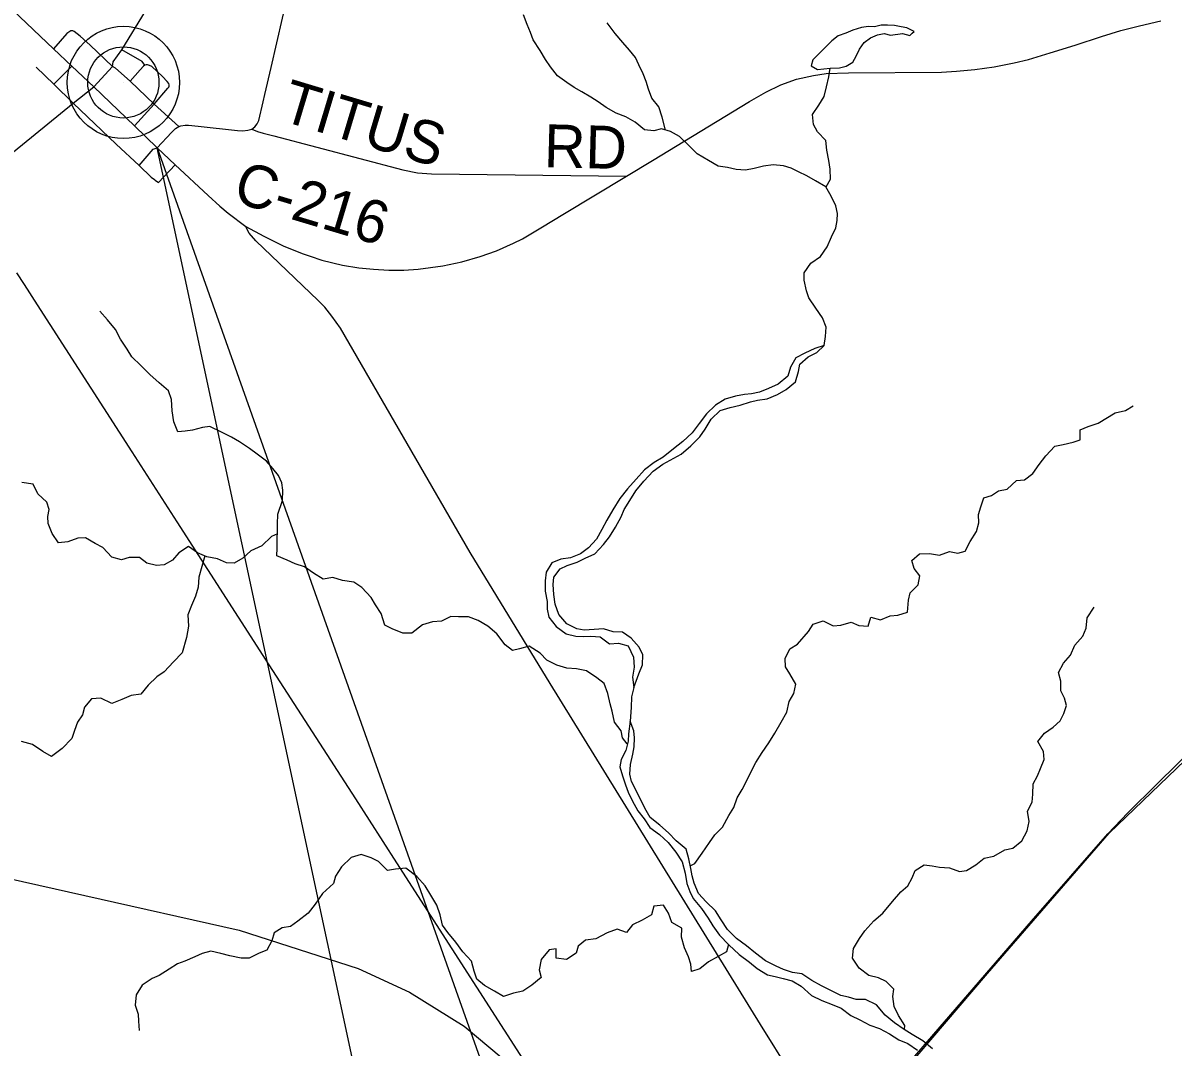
# Model space of a CAD drawing. Extents: x 0 to 34, y 0 to 22.
# Drawn here: x 4.77 to 5.532, y 15.329 to 16.008 of the extents above; entities that cross this region are included whole.
import ezdxf

# ---------------------------------------------------------------- set-up
doc = ezdxf.new("R2010")
doc.units = 0
for name, color, linetype in [('GM_X_County_Road', 7, 'Continuous'), ('GM_X_County_Road_Text', 7, 'Continuous'), ('GM_X_Minor_Lake', 7, 'Continuous'), ('GM_X_Minor_River', 7, 'Continuous'), ('GM_X_Rail_Line', 7, 'Continuous'), ('GM_X_State_Route', 7, 'Continuous'), ('GM_X_Township_Road', 7, 'Continuous'), ('GM_X_Unincorporated', 7, 'Continuous'), ('GM_X_Unincorporated_Location', 7, 'Continuous'), ('SH_Text', 7, 'Continuous')]:
    doc.layers.add(name, color=color, linetype=linetype)

msp = doc.modelspace()

# ---------------------------------------------------------------- linework, layer by layer
at = {"layer": 'GM_X_County_Road'}
for points in [[(4.92188, 15.93736), (4.92553, 15.93572), (4.9293, 15.93457), (4.9363, 15.93294), (5.02191, 15.91045), (5.03158, 15.90846), (5.04097, 15.90761), (5.17016, 15.90625)], [(5.57836, 15.08677), (5.48556, 15.13609), (5.4293, 15.16578), (5.41883, 15.1717), (5.40807, 15.17885), (5.38156, 15.19893), (5.37557, 15.20405), (5.36741, 15.2125), (5.35766, 15.22305), (5.33768, 15.24534), (5.31683, 15.26876), (5.30209, 15.28504), (5.27906, 15.31173), (5.25891, 15.34383), (5.11957, 15.56983), (5.06651, 15.65664), (4.98053, 15.80534), (4.97493, 15.81333), (4.97028, 15.81941), (4.96586, 15.82383), (4.92435, 15.86339), (4.92003, 15.86847), (4.91864, 15.87087), (4.91787, 15.87287)]]:
    msp.add_lwpolyline(points, dxfattribs=at)
at = {"layer": 'GM_X_Minor_Lake'}
for points in [[(5.35947, 16.00091), (5.36068, 16.00195), (5.35595, 16.00443), (5.35216, 16.0052), (5.34781, 16.00598), (5.34308, 16.00618), (5.33891, 16.0062), (5.33455, 16.00526), (5.33057, 16.00528), (5.32583, 16.00473), (5.32014, 16.00285), (5.3154, 16.00097), (5.31047, 15.99909), (5.30629, 15.99588), (5.29355, 15.98321), (5.29259, 15.97923), (5.29674, 15.97694), (5.30508, 15.97767)], [(5.30508, 15.97767), (5.31133, 15.97803), (5.3157, 15.97915), (5.32006, 15.98179), (5.32235, 15.98577), (5.32464, 15.99031), (5.32769, 15.99467), (5.33187, 15.99788), (5.33642, 15.99976), (5.34097, 16.00069), (5.34513, 15.99954), (5.35309, 16.00065), (5.35783, 15.99949), (5.35947, 16.00091)]]:
    msp.add_lwpolyline(points, dxfattribs=at)
at = {"layer": 'GM_X_Minor_River'}
for points in [[(5.30114, 15.79393), (5.30193, 15.79981), (5.30253, 15.80606), (5.29992, 15.81234), (5.29559, 15.81862), (5.2909, 15.82547), (5.28941, 15.83022), (5.28793, 15.83724), (5.28777, 15.84218), (5.29235, 15.84841), (5.29862, 15.85293), (5.30302, 15.85935), (5.30589, 15.86598), (5.30877, 15.87184), (5.30974, 15.87677), (5.30996, 15.88151), (5.30885, 15.88645), (5.30585, 15.89291), (5.30229, 15.89919), (5.2953, 15.90302), (5.28964, 15.90646), (5.28416, 15.90914), (5.27925, 15.91145), (5.27414, 15.91299), (5.26733, 15.91378), (5.26088, 15.91287), (5.25481, 15.9112), (5.24893, 15.91009), (5.24288, 15.9105), (5.23701, 15.91186), (5.23077, 15.91284), (5.22454, 15.91648), (5.21698, 15.92107), (5.21152, 15.92641), (5.2053, 15.93251), (5.19926, 15.93576), (5.1934, 15.9375), (5.18828, 15.9362), (5.18203, 15.9368), (5.17581, 15.94196), (5.16958, 15.94541), (5.16334, 15.9479), (5.15654, 15.95173), (5.15145, 15.95536), (5.14654, 15.95861), (5.1405, 15.96206), (5.1354, 15.96493), (5.1305, 15.96818), (5.12446, 15.97258), (5.11976, 15.97867), (5.11637, 15.98343), (5.11281, 15.98952), (5.1083, 15.99656), (5.10643, 16.0015), (5.10438, 16.00663), (5.10195, 16.01309)], [(5.19594, 15.93675), (5.19376, 15.94525), (5.19152, 15.95208), (5.1868, 15.95798), (5.18474, 15.96387), (5.18324, 15.96899), (5.18118, 15.97393), (5.17836, 15.98001), (5.1761, 15.98476), (5.17215, 15.98971), (5.16762, 15.99484), (5.16253, 16.00074), (5.15725, 16.00778)], [(5.30238, 15.89903), (5.30537, 15.90408), (5.30502, 15.91091), (5.30428, 15.9166), (5.30298, 15.92343), (5.30225, 15.92989), (5.29678, 15.93559), (5.29414, 15.94035), (5.29341, 15.94699), (5.2976, 15.95323), (5.30103, 15.95891), (5.30276, 15.96535), (5.30411, 15.97199), (5.30508, 15.97767)], [(5.17065, 15.52981), (5.16745, 15.5339), (5.16652, 15.53864), (5.16218, 15.54435), (5.1607, 15.55157), (5.1592, 15.5565), (5.15771, 15.56334), (5.15527, 15.5698), (5.15035, 15.57361), (5.14355, 15.57838), (5.13692, 15.57954), (5.13068, 15.58013), (5.12386, 15.58205), (5.11724, 15.5853), (5.1129, 15.59006), (5.10572, 15.59464), (5.09927, 15.59295), (5.09454, 15.59183), (5.08962, 15.59564), (5.08416, 15.60287), (5.0783, 15.60801), (5.07187, 15.61164), (5.06544, 15.61413), (5.05881, 15.61415), (5.0537, 15.61436), (5.04743, 15.61116), (5.04156, 15.6108), (5.03492, 15.60874), (5.02789, 15.60326), (5.02183, 15.60328), (5.01483, 15.60616), (5.00992, 15.60864), (5.00748, 15.61624), (5.00371, 15.62213), (5.00089, 15.62688), (4.99466, 15.63355), (4.98937, 15.63717), (4.98199, 15.63814), (4.97555, 15.64025), (4.96911, 15.63914), (4.96268, 15.64296), (4.95663, 15.64715), (4.95058, 15.64926), (4.94528, 15.65175), (4.93847, 15.65443), (4.93849, 15.65955), (4.93851, 15.666), (4.93891, 15.67074), (4.93893, 15.67548), (4.93914, 15.68212), (4.9422, 15.69121), (4.94242, 15.69804), (4.94168, 15.70298), (4.93942, 15.70773), (4.93565, 15.71248), (4.9315, 15.71724), (4.92526, 15.72182), (4.92016, 15.72563), (4.91355, 15.73002), (4.90826, 15.73307), (4.90164, 15.73651), (4.89388, 15.74014), (4.88915, 15.73959), (4.88251, 15.73791), (4.87758, 15.73717), (4.87284, 15.7368), (4.87022, 15.74345), (4.86911, 15.75066), (4.86857, 15.75806), (4.8665, 15.76395), (4.86046, 15.7691), (4.85423, 15.77481), (4.84819, 15.78071), (4.84234, 15.78642), (4.83913, 15.79156), (4.8348, 15.79821), (4.83142, 15.80448), (4.82614, 15.81095), (4.82104, 15.81666)], [(5.30114, 15.79393), (5.29488, 15.79188), (5.28824, 15.78888), (5.28235, 15.78568), (5.2789, 15.77963), (5.27698, 15.77357), (5.2707, 15.7683), (5.26424, 15.76549), (5.25817, 15.76305), (5.25305, 15.76194), (5.24831, 15.7614), (5.24243, 15.76029), (5.2356, 15.75843), (5.22914, 15.75448), (5.22305, 15.74863), (5.21828, 15.74221), (5.2137, 15.73616), (5.20742, 15.73032), (5.20133, 15.72542), (5.19448, 15.71996), (5.1884, 15.71638), (5.18194, 15.71149), (5.1766, 15.70545), (5.17088, 15.69903), (5.16573, 15.69242), (5.16115, 15.68504), (5.15713, 15.67824), (5.15388, 15.67199), (5.15025, 15.66557), (5.14491, 15.6599), (5.13959, 15.65576), (5.13294, 15.65314), (5.12669, 15.65222), (5.12061, 15.64998), (5.11698, 15.64374), (5.11619, 15.63786), (5.11616, 15.63104), (5.11745, 15.6242), (5.11761, 15.61927), (5.11872, 15.61395), (5.12342, 15.60767), (5.13021, 15.60289), (5.13645, 15.60134), (5.14157, 15.60112), (5.14649, 15.60128), (5.15274, 15.60087), (5.15878, 15.5961), (5.16484, 15.59663), (5.17127, 15.59489), (5.17483, 15.58747), (5.17517, 15.58064), (5.174, 15.57401), (5.17491, 15.56718)], [(5.17491, 15.56718), (5.17837, 15.57626), (5.18068, 15.58232), (5.1809, 15.58896), (5.17847, 15.59409), (5.17319, 15.6), (5.16753, 15.60402), (5.16128, 15.60424), (5.15485, 15.60617), (5.1486, 15.60563), (5.14216, 15.60529), (5.13724, 15.60607), (5.13063, 15.60952), (5.12536, 15.61562), (5.12274, 15.62246), (5.12202, 15.62892), (5.12148, 15.63556), (5.12189, 15.64049), (5.12609, 15.64597), (5.13083, 15.64822), (5.13747, 15.65027), (5.14279, 15.6529), (5.14906, 15.6559), (5.15496, 15.66212), (5.15878, 15.66704), (5.16279, 15.67346), (5.16661, 15.68027), (5.16854, 15.68519), (5.17236, 15.69124), (5.17637, 15.69767), (5.18152, 15.70409), (5.1878, 15.7107), (5.19427, 15.71521), (5.20624, 15.72198), (5.21271, 15.72745), (5.2188, 15.73329), (5.22224, 15.7384), (5.22625, 15.74501), (5.23215, 15.75086), (5.23879, 15.75291), (5.24543, 15.75439), (5.25226, 15.75664), (5.257, 15.75775), (5.26326, 15.75866), (5.27028, 15.76147), (5.27598, 15.76485), (5.28207, 15.76994), (5.28419, 15.77676), (5.28497, 15.7815), (5.29049, 15.7864), (5.29619, 15.78921), (5.30114, 15.79393)], [(5.21237, 15.44909), (5.2154, 15.45068), (5.22036, 15.45748), (5.22513, 15.46447), (5.22876, 15.46958), (5.23371, 15.47467), (5.23792, 15.48243), (5.24116, 15.48772), (5.24347, 15.49416), (5.24672, 15.49964), (5.24978, 15.5057), (5.25304, 15.51194), (5.25591, 15.51762), (5.26011, 15.52423), (5.2645, 15.53066), (5.26832, 15.53709), (5.27252, 15.54427), (5.27635, 15.55089), (5.2779, 15.5579), (5.28096, 15.5632), (5.28232, 15.56945), (5.27838, 15.5763), (5.27556, 15.58106), (5.27521, 15.58656), (5.27828, 15.59281), (5.28341, 15.596), (5.29065, 15.60431), (5.2939, 15.60923), (5.30054, 15.61147), (5.30715, 15.60802), (5.31207, 15.60856), (5.31909, 15.61061), (5.324, 15.60831), (5.33025, 15.60789), (5.33199, 15.61377), (5.33842, 15.61221), (5.34487, 15.61465), (5.34999, 15.61519), (5.35625, 15.61724), (5.35705, 15.6252), (5.35802, 15.62994), (5.36336, 15.63523), (5.36452, 15.64129), (5.36076, 15.64605), (5.35928, 15.65137), (5.36441, 15.65589), (5.37085, 15.65605), (5.37748, 15.65507), (5.38412, 15.65731), (5.3898, 15.65633), (5.39454, 15.65763), (5.39779, 15.66407), (5.402, 15.67068), (5.40354, 15.67636), (5.40338, 15.68187), (5.40492, 15.68698), (5.40704, 15.69304), (5.41197, 15.69453), (5.41672, 15.69754), (5.42241, 15.69865), (5.42869, 15.7045), (5.43381, 15.70485), (5.43952, 15.70899), (5.44352, 15.71504), (5.4481, 15.72071), (5.45401, 15.72731), (5.45951, 15.72823), (5.46614, 15.72991), (5.47089, 15.7314), (5.47073, 15.73804), (5.47605, 15.74029), (5.48269, 15.74253), (5.49409, 15.7493), (5.50073, 15.75078), (5.50586, 15.75398)], [(4.93877, 15.66903), (4.93492, 15.66734), (4.92846, 15.6611), (4.92125, 15.6579), (4.91592, 15.65299), (4.91004, 15.6496), (4.90511, 15.6498), (4.89906, 15.65248), (4.89206, 15.65384), (4.88582, 15.65651), (4.87977, 15.66071), (4.8735, 15.65656), (4.86913, 15.65164), (4.86381, 15.64863), (4.8587, 15.64808), (4.85226, 15.64962), (4.84735, 15.65343), (4.84053, 15.65346), (4.83541, 15.65196), (4.82898, 15.65369), (4.82313, 15.65997), (4.81802, 15.66264), (4.81159, 15.66646), (4.80648, 15.66629), (4.79984, 15.66385), (4.79358, 15.66311), (4.78944, 15.66939), (4.78681, 15.67585), (4.78664, 15.68059), (4.78741, 15.68533), (4.78591, 15.69008), (4.78006, 15.6956), (4.77686, 15.70206), (4.76948, 15.70304)], [(4.89064, 15.65445), (4.88863, 15.6474), (4.88671, 15.64039), (4.8863, 15.63375), (4.88439, 15.62787), (4.88172, 15.62162), (4.87942, 15.61537), (4.87977, 15.60797), (4.87861, 15.60039), (4.87554, 15.59015), (4.86984, 15.58429), (4.86375, 15.57768), (4.85882, 15.57428), (4.85311, 15.5688), (4.84817, 15.56294), (4.84191, 15.56201), (4.83565, 15.55938), (4.82901, 15.55655), (4.82183, 15.56019), (4.81557, 15.55964), (4.81101, 15.55415), (4.80966, 15.54923), (4.80624, 15.54431), (4.80433, 15.53881), (4.80241, 15.53351), (4.79614, 15.52689), (4.78911, 15.5216), (4.78325, 15.52485), (4.77645, 15.52943), (4.76907, 15.53154)], [(5.35432, 15.34061), (5.35462, 15.34332), (5.3503, 15.3498), (5.34749, 15.35588), (5.34657, 15.36253), (5.34736, 15.36727), (5.34227, 15.37241), (5.33717, 15.37472), (5.33074, 15.37646), (5.32432, 15.38124), (5.31981, 15.3879), (5.3206, 15.39435), (5.32461, 15.40096), (5.32805, 15.40607), (5.33415, 15.41249), (5.34004, 15.41758), (5.34633, 15.42551), (5.35186, 15.43174), (5.35662, 15.4357), (5.35949, 15.441), (5.3614, 15.44592), (5.36749, 15.44968), (5.3726, 15.44909), (5.37752, 15.44811), (5.38414, 15.4477), (5.39076, 15.4452), (5.3955, 15.44593), (5.40158, 15.44969), (5.40709, 15.45403), (5.41354, 15.45551), (5.42076, 15.45965), (5.42607, 15.46076), (5.43215, 15.46566), (5.4356, 15.47228), (5.43696, 15.47853), (5.43586, 15.48537), (5.43892, 15.49123), (5.43933, 15.49654), (5.43955, 15.50337), (5.44242, 15.50866), (5.44453, 15.51359), (5.44683, 15.51964), (5.44648, 15.52477), (5.44273, 15.53143), (5.44712, 15.53709), (5.45282, 15.54086), (5.45758, 15.5452), (5.46007, 15.55011), (5.4618, 15.55523), (5.46031, 15.56017), (5.45787, 15.56511), (5.45791, 15.57156), (5.45642, 15.57726), (5.45967, 15.58331), (5.46444, 15.58879), (5.46731, 15.59522), (5.47265, 15.60127), (5.47476, 15.60657), (5.47537, 15.61339), (5.48014, 15.62039)], [(5.17491, 15.56718), (5.17336, 15.56112), (5.17314, 15.55391), (5.17252, 15.545)], [(5.17252, 15.545), (5.17153, 15.53646), (5.17113, 15.53173), (5.16958, 15.52547), (5.16652, 15.51961), (5.16573, 15.51468), (5.16741, 15.50879), (5.16946, 15.50271), (5.17114, 15.49777), (5.17395, 15.49225), (5.1777, 15.48559), (5.18184, 15.48026), (5.1856, 15.47436), (5.19201, 15.46977), (5.19767, 15.46443), (5.20275, 15.45814), (5.20707, 15.45167), (5.20893, 15.44426), (5.21003, 15.43743), (5.21208, 15.4321), (5.21433, 15.42735), (5.21979, 15.42087), (5.2243, 15.4144), (5.22731, 15.40926), (5.23182, 15.40316), (5.23785, 15.39668), (5.24482, 15.39038), (5.25161, 15.38523), (5.25671, 15.38102), (5.2635, 15.37682), (5.26861, 15.37565), (5.27391, 15.37448), (5.27996, 15.37274), (5.28581, 15.3693), (5.29279, 15.36319), (5.29959, 15.35974), (5.30639, 15.35724), (5.31244, 15.35474), (5.31886, 15.34996), (5.32471, 15.34709), (5.33132, 15.34345), (5.33775, 15.34114), (5.34436, 15.33769), (5.35059, 15.33367), (5.35664, 15.33136), (5.36305, 15.32677)], [(5.37291, 15.32767), (5.3665, 15.33302), (5.35951, 15.33723), (5.35423, 15.34067), (5.34781, 15.34507), (5.34158, 15.35003), (5.33575, 15.35689), (5.32857, 15.36053), (5.32232, 15.36038), (5.31722, 15.36211), (5.31211, 15.36309), (5.29926, 15.36961), (5.29284, 15.37305), (5.28642, 15.37745), (5.28018, 15.37843), (5.27413, 15.38036), (5.26921, 15.38248), (5.26222, 15.38612), (5.25562, 15.39109), (5.24959, 15.39605), (5.24298, 15.40083), (5.23714, 15.40693), (5.23282, 15.41321), (5.22906, 15.4193), (5.22284, 15.42522), (5.21776, 15.43075), (5.21495, 15.43759), (5.21365, 15.44253), (5.21273, 15.44728), (5.21144, 15.45373), (5.20977, 15.46), (5.20298, 15.46573), (5.19789, 15.47088), (5.19224, 15.47603), (5.18582, 15.481), (5.1832, 15.48575), (5.18038, 15.49127), (5.17701, 15.49812), (5.17345, 15.50496), (5.17234, 15.50971), (5.17275, 15.51616), (5.1743, 15.52298), (5.17527, 15.52791), (5.17549, 15.53379), (5.17495, 15.53853), (5.17252, 15.545)], [(5.23767, 15.39688), (5.23629, 15.39212), (5.23098, 15.38891), (5.22452, 15.38533), (5.21883, 15.3808), (5.21314, 15.37911), (5.21278, 15.38385), (5.21128, 15.38879), (5.20865, 15.39468), (5.20659, 15.40171), (5.2068, 15.40778), (5.20018, 15.41141), (5.19793, 15.41768), (5.19472, 15.423), (5.18828, 15.42227), (5.18675, 15.41658), (5.18048, 15.413), (5.17403, 15.40999), (5.17004, 15.40488), (5.16398, 15.40718), (5.15734, 15.40454), (5.14975, 15.40058), (5.14293, 15.39985), (5.13799, 15.39588), (5.13684, 15.39114), (5.13039, 15.38699), (5.12357, 15.38778), (5.12359, 15.39404), (5.11885, 15.39329), (5.11353, 15.38686), (5.11218, 15.38023), (5.11349, 15.3751), (5.10741, 15.37), (5.10152, 15.36603), (5.09527, 15.36473), (5.08863, 15.36248), (5.08258, 15.36591), (5.07596, 15.36973), (5.07086, 15.37392), (5.06918, 15.37924), (5.0673, 15.38589), (5.06164, 15.39198), (5.05693, 15.39845), (5.05165, 15.40492), (5.04825, 15.40967), (5.04657, 15.41651), (5.04432, 15.42297), (5.04036, 15.42962), (5.03679, 15.4359), (5.03112, 15.44199), (5.02394, 15.44752), (5.01712, 15.44678), (5.01181, 15.44585), (5.00577, 15.45195), (5.00086, 15.45443), (4.99423, 15.45654), (4.9876, 15.45467), (4.98114, 15.44843), (4.97733, 15.44218), (4.97598, 15.43725), (4.96857, 15.43064), (4.96381, 15.42364), (4.95925, 15.41777), (4.95222, 15.41229), (4.94747, 15.4089), (4.94198, 15.40797), (4.93666, 15.40457), (4.93513, 15.39926), (4.9317, 15.3932), (4.92677, 15.39114), (4.92012, 15.38793), (4.91482, 15.38776), (4.90725, 15.38931), (4.90119, 15.39085), (4.89457, 15.39239), (4.88888, 15.39089), (4.88395, 15.38863), (4.87731, 15.38581), (4.87257, 15.38412), (4.86706, 15.38053), (4.86042, 15.37639), (4.85567, 15.37432), (4.84903, 15.36997), (4.84522, 15.36354), (4.84444, 15.35671), (4.8465, 15.35082), (4.84668, 15.34608), (4.84722, 15.33981)]]:
    msp.add_lwpolyline(points, dxfattribs=at)
at = {"layer": 'GM_X_Rail_Line'}
for points in [[(5.26583, 15.2105), (5.33567, 15.29137), (5.40941, 15.37775), (5.48991, 15.47067), (5.6406, 15.6155), (5.83424, 15.80173), (6.18812, 16.14257), (6.45824, 16.40221), (6.73523, 16.66813), (7.01365, 16.93639), (7.24354, 17.1561), (7.44209, 17.35095), (7.62627, 17.52649), (7.92956, 17.8183), (8.07725, 17.96232), (8.43659, 18.30894), (8.70085, 18.56216), (8.9, 18.75531)], [(2.87249, 15.85698), (2.91145, 15.85791), (2.96133, 15.85164), (2.99463, 15.84452), (3.20808, 15.79503), (3.74918, 15.67048), (3.93017, 15.6314), (4.30003, 15.5466), (4.60627, 15.4754), (4.9134, 15.40633), (4.99239, 15.38104), (5.02639, 15.36542), (5.06261, 15.34269), (5.08696, 15.3222), (5.12288, 15.28684)], [(5.30918, 14.99809), (5.26841, 15.06169), (5.21253, 15.14817), (5.19961, 15.16836), (5.18483, 15.19134), (5.17906, 15.20066), (5.01796, 15.45104), (4.99067, 15.49354), (4.93323, 15.58238), (4.87238, 15.67701), (4.84244, 15.72356), (4.77984, 15.82092), (4.77125, 15.83439), (4.76602, 15.84214)], [(5.17906, 15.20066), (5.18762, 15.19243), (5.19292, 15.18956), (5.20167, 15.18525), (5.20887, 15.18361), (5.2189, 15.18288), (5.22976, 15.18526), (5.2378, 15.18846), (5.24711, 15.19384), (5.25535, 15.20079), (5.30395, 15.25624), (5.35416, 15.31465), (5.43851, 15.4124), (5.48918, 15.47034), (5.50235, 15.48427), (5.52153, 15.50329), (5.54912, 15.53036), (5.57527, 15.55588), (5.60095, 15.58047), (5.63138, 15.60922), (5.6821, 15.65824), (5.77069, 15.74376), (5.82188, 15.79325), (5.83531, 15.80567)]]:
    msp.add_lwpolyline(points, dxfattribs=at)
at = {"layer": 'GM_X_State_Route'}
for p, q in [((4.81704, 15.96533), (4.84396, 15.93957)), ((4.84396, 15.93957), (4.85905, 15.92505))]:
    msp.add_line(p, q, dxfattribs=at)
for points in [[(4.60955, 16.11795), (4.61443, 16.11682), (4.6373, 16.11157), (4.6488, 16.10808), (4.65747, 16.10487), (4.66562, 16.10119), (4.67259, 16.09737), (4.68086, 16.09218), (4.68882, 16.08634), (4.69637, 16.07976), (4.79027, 15.99067), (4.80249, 15.97917), (4.81704, 15.96533)], [(4.93042, 15.96027), (4.93453, 15.97828), (4.95712, 16.07642), (4.96626, 16.11597)], [(4.96038, 15.85309), (4.96813, 15.85054), (4.9818, 15.84717), (4.99276, 15.84548), (5.00255, 15.84447), (5.01267, 15.84396), (5.02245, 15.84396), (5.03207, 15.84464), (5.04843, 15.84683), (5.06109, 15.84936), (5.07323, 15.8529), (5.08403, 15.85678), (5.09533, 15.86167), (5.10124, 15.86471), (5.11452, 15.87256), (5.12785, 15.88071), (5.17016, 15.90625), (5.18727, 15.91662), (5.25166, 15.95565), (5.26245, 15.9618), (5.27234, 15.96664), (5.28272, 15.97037), (5.29401, 15.97299), (5.30239, 15.97415), (5.31731, 15.97471), (5.37891, 15.97511), (5.38879, 15.97571), (5.401, 15.97682), (5.4139, 15.97874), (5.42701, 15.98136), (5.43649, 15.98358), (5.45101, 15.98781), (5.46754, 15.99296), (5.48489, 15.9987), (5.49779, 16.00264), (5.5102, 16.00576), (5.52418, 16.00919)], [(4.66541, 15.84218), (4.80339, 15.95445), (4.81704, 15.96533)], [(4.85905, 15.92505), (4.86846, 15.93501), (4.8712, 15.93775), (4.87342, 15.93899), (4.87483, 15.93963), (4.87773, 15.94001), (4.87976, 15.93988), (4.88627, 15.93937), (4.91233, 15.93648), (4.91584, 15.93623), (4.91924, 15.93661), (4.92188, 15.93736), (4.9238, 15.93897), (4.92539, 15.94094), (4.92651, 15.94314), (4.9293, 15.9554), (4.93042, 15.96027)], [(4.85905, 15.92505), (4.87099, 15.91374), (4.89276, 15.89331), (4.90065, 15.88625), (4.90619, 15.88159), (4.91787, 15.87287), (4.92984, 15.8664), (4.94299, 15.85982), (4.95582, 15.85459), (4.96038, 15.85309)]]:
    msp.add_lwpolyline(points, dxfattribs=at)
at = {"layer": 'GM_X_Township_Road'}
for p, q in [((4.7905, 15.96714), (4.80249, 15.97917)), ((4.81704, 15.96533), (4.82939, 15.97879))]:
    msp.add_line(p, q, dxfattribs=at)
for points in [[(4.82939, 15.97879), (4.82988, 15.98187), (4.83558, 15.98998), (4.85133, 16.01543)], [(4.87342, 15.93899), (4.85707, 15.95381), (4.84109, 15.96905), (4.83146, 15.97768), (4.82939, 15.97879), (4.8146, 15.99297), (4.8081, 15.99894), (4.80416, 16.00209), (4.80315, 16.00253), (4.80191, 16.00258), (4.80044, 16.00172), (4.79912, 16.00065), (4.79027, 15.99067)], [(4.85097, 15.97979), (4.84917, 15.9822), (4.83558, 15.98998)], [(4.77891, 15.9784), (4.7905, 15.96714), (4.80339, 15.95445)], [(4.84396, 15.93957), (4.85707, 15.95381), (4.8662, 15.96443), (4.8668, 15.9652), (4.86706, 15.96588), (4.8671, 15.96679), (4.86682, 15.96759), (4.86563, 15.96892), (4.86256, 15.97224), (4.85551, 15.97879), (4.85402, 15.97963), (4.85274, 15.97999), (4.85179, 15.97998), (4.85097, 15.97979), (4.84998, 15.97912), (4.8478, 15.97674), (4.84109, 15.96905)], [(4.80339, 15.95445), (4.83179, 15.92746), (4.84704, 15.91322), (4.85504, 15.90553), (4.85726, 15.90389), (4.85764, 15.9036)], [(4.84704, 15.91322), (4.85631, 15.924), (4.85905, 15.92505)], [(4.85764, 15.9036), (4.85991, 15.90187), (4.87099, 15.91374)]]:
    msp.add_lwpolyline(points, dxfattribs=at)
at = {"layer": 'GM_X_Unincorporated'}
for radius in [0.0372, 0.02358]:
    msp.add_circle((4.83668, 15.96829), radius, dxfattribs=at)
at = {"layer": 'GM_X_Unincorporated_Location'}
msp.add_line((4.83668, 15.96829), (4.83668, 15.96829), dxfattribs=at)
at = {"layer": 'SH_Text'}
msp.add_lwpolyline([(5.19712, 14.34788), (4.85905, 15.92505), (5.19712, 14.97163)], close=True, dxfattribs=at)

# ---------------------------------------------------------------- texts
at = {"layer": 'GM_X_County_Road_Text'}
for s, rotation, p in [('TITUS', 343.25419, (4.93977, 15.94342)), ('RD', 358.50456, (5.11517, 15.91222)), ('C-216', 343.30046, (4.9082, 15.88959))]:
    msp.add_text(s, height=0.028409, rotation=rotation, dxfattribs=at).set_placement(p)

doc.saveas('drawing.dxf')
